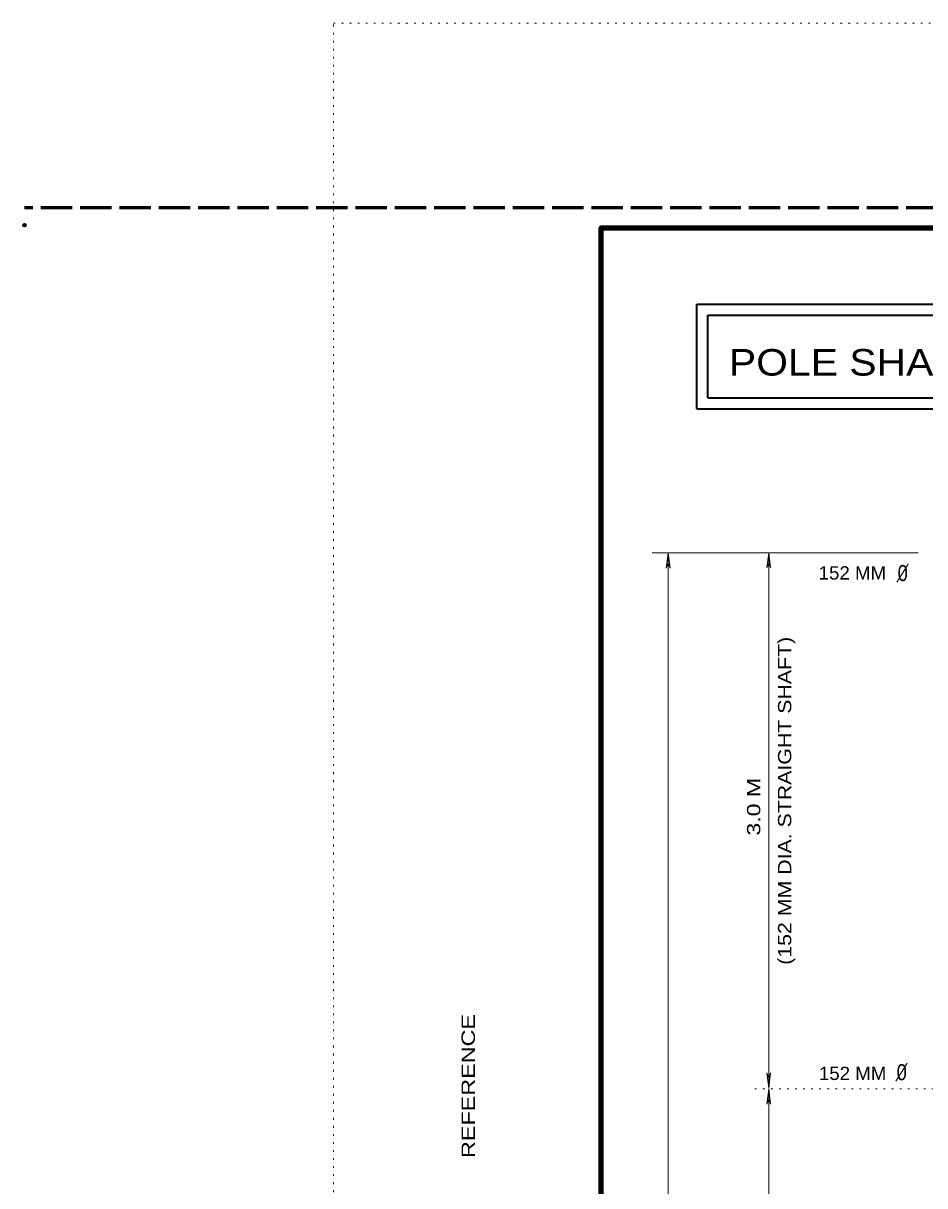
# Model space of a CAD drawing. Extents: x 312583 to 312854, y 144419 to 144597.
# Drawn here: x 312583.5 to 312635, y 144530.3 to 144596.8 of the extents above; entities that cross this region are included whole.
import ezdxf
from ezdxf.enums import TextEntityAlignment as Align

# ---------------------------------------------------------------- set-up
doc = ezdxf.new("R2010")
doc.units = 0
doc.header["$LTSCALE"] = 0.3
doc.header["$PDMODE"] = 32
doc.header["$PDSIZE"] = 0.15
doc.linetypes.add('DOTTED', pattern=[1.5, 0.3, -1.2])
doc.linetypes.add('LONG_DASHED', pattern=[7.5, 6, -1.5])
for name, color, linetype, lineweight in [('1', 7, 'Continuous', 35), ('2', 7, 'Continuous', 13), ('62', 7, 'DOTTED', 13), ('63', 7, 'LONG_DASHED', 60)]:
    doc.layers.add(name, color=color, linetype=linetype, lineweight=lineweight)

msp = doc.modelspace()

# ---------------------------------------------------------------- linework, layer by layer
at = {"layer": '1', "linetype": 'DOTTED', "lineweight": 13}
msp.add_line((312636.4377, 144535.8063), (312625.1524, 144535.8063), dxfattribs=at)
at = {"layer": '1', "lineweight": 158}
msp.add_lwpolyline([(312616.5, 144423.1446), (312616.5, 144585.0846), (312849, 144585.0846)], dxfattribs=at)
at = {"layer": '1'}
msp.add_point((312583.526, 144585.2246), dxfattribs=at)
at = {"layer": '2', "lineweight": 35}
for p, q in [((312621.9732, 144580.7176), (312680.1273, 144580.7176)), ((312621.9732, 144574.7262), (312621.9732, 144580.7176)), ((312622.6019, 144580.0889), (312679.491, 144580.0889)), ((312622.6019, 144575.3549), (312622.6019, 144580.0889)), ((312622.6019, 144575.3549), (312679.491, 144575.3549))]:
    msp.add_line(p, q, dxfattribs=at)
at = {"layer": '2'}
for p, q in [((312634.636, 144566.473), (312619.4177, 144566.473)), ((312620.3377, 144566.473), (312620.2304, 144565.6066)), ((312620.3377, 144441.2533), (312620.3377, 144566.473)), ((312620.3377, 144566.473), (312620.445, 144565.6066)), ((312626.0877, 144566.4806), (312625.9804, 144565.6143)), ((312626.0877, 144566.4806), (312626.195, 144565.6143)), ((312626.0877, 144535.8523), (312626.0877, 144566.4806)), ((312620.2304, 144565.6066), (312620.3377, 144565.8826)), ((312620.445, 144565.6066), (312620.3377, 144565.8826)), ((312625.9804, 144565.6143), (312626.0877, 144565.8903)), ((312626.195, 144565.6143), (312626.0877, 144565.8903)), ((312633.4242, 144564.8112), (312634.0605, 144565.8309)), ((312633.3667, 144536.251), (312634.003, 144537.2706)), ((312625.9804, 144536.7186), (312626.0877, 144536.4426)), ((312626.0877, 144535.8523), (312625.9804, 144536.7186)), ((312626.195, 144536.7186), (312626.0877, 144536.4426)), ((312626.0877, 144535.8523), (312626.195, 144536.7186)), ((312626.0877, 144535.8063), (312625.9804, 144534.94)), ((312626.0877, 144535.8063), (312626.195, 144534.94)), ((312626.0877, 144471.92), (312626.0877, 144535.7756)), ((312625.9804, 144534.94), (312626.0877, 144535.216)), ((312626.195, 144534.94), (312626.0877, 144535.216))]:
    msp.add_line(p, q, dxfattribs=at)
at = {"layer": '2', "lineweight": 35}
msp.add_lwpolyline([(312621.9732, 144574.7262), (312680.1273, 144574.7262), (312680.1273, 144580.7176)], dxfattribs=at)
at = {"layer": '62'}
for p, q in [((312601.2, 144596.7846), (312853.5, 144596.7846)), ((312601.2, 144418.5846), (312601.2, 144596.7846))]:
    msp.add_line(p, q, dxfattribs=at)
at = {"layer": '63'}
msp.add_line((312851.75, 144586.2246), (312583.526, 144586.2246), dxfattribs=at)

# ---------------------------------------------------------------- texts
at = {"layer": '1', "width": 1.3}
msp.add_text('REFERENCE                                                              ', height=0.7682, rotation=90, dxfattribs=at).set_placement((312609.2854, 144531.8549))
at = {"layer": '2'}
for s, height, width, p in [('POLE SHALL NOT BE INSTALLED WITHOUT ARM', 1.52, 1.15, (312651.0228, 144576.6219)), ('0', 0.92, 0.85, (312633.7538, 144564.8649)), ('0', 0.92, 0.85, (312633.6964, 144536.3046))]:
    msp.add_text(s, height=height, dxfattribs=dict(at, width=width)).set_placement(p, align=Align.CENTER)
at = {"layer": '2', "width": 1.05}
for p in [(312628.9458, 144564.954), (312628.9596, 144536.3167)]:
    msp.add_text('152 MM', height=0.76, dxfattribs=at).set_placement(p)
at = {"layer": '2'}
for s, width, p in [('(152 MM DIA. STRAIGHT SHAFT)', 1.2, (312627.3785, 144542.9073)), ('3.0 M', 1.3, (312625.6063, 144550.2996))]:
    msp.add_text(s, height=0.76, rotation=90, dxfattribs=dict(at, width=width)).set_placement(p)

doc.saveas('drawing.dxf')
